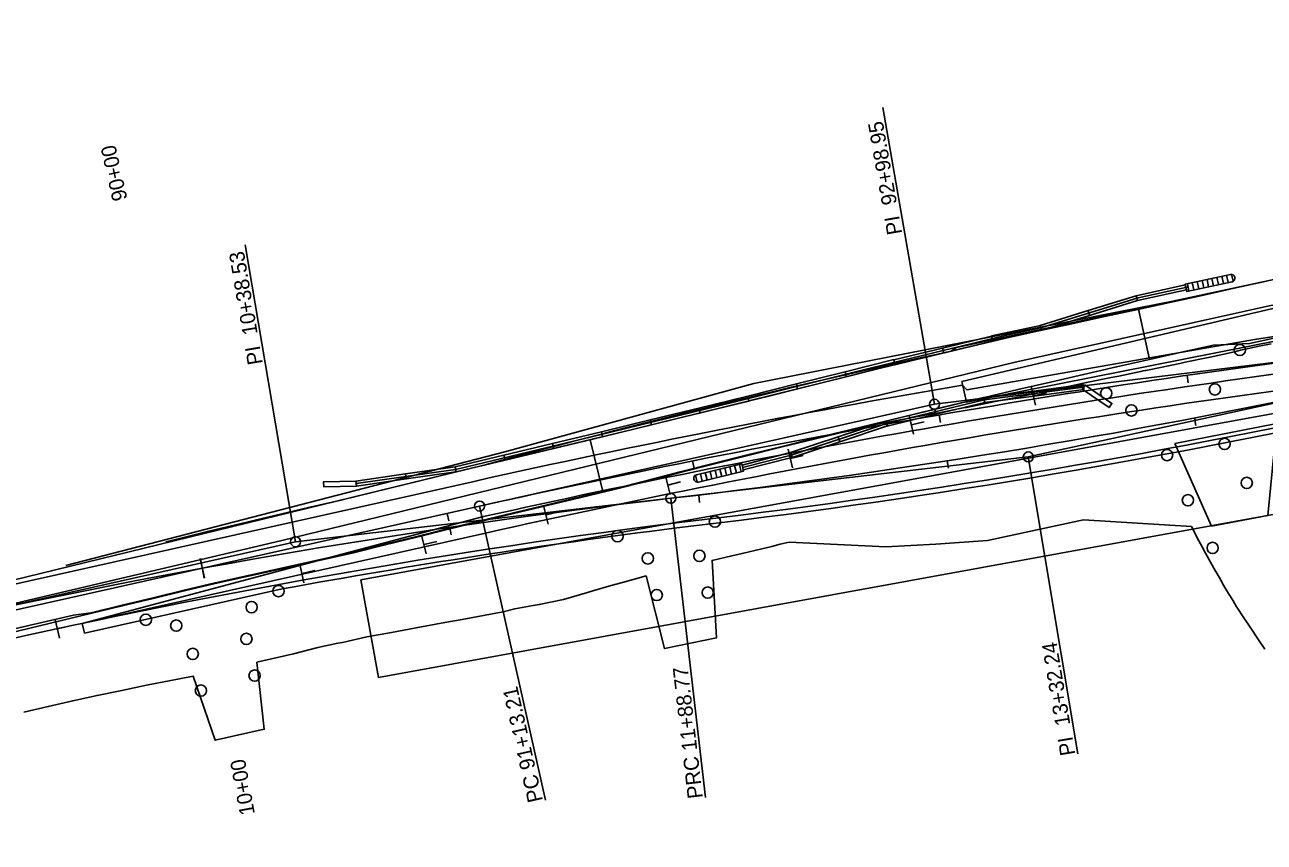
# Model space of a CAD drawing. Extents: x 1568809 to 1572786, y 728326 to 734907.
# Drawn here: x 1569227.8 to 1569721.8, y 731921.7 to 732247.4 of the extents above; entities that cross this region are included whole.
import ezdxf

# ---------------------------------------------------------------- set-up
doc = ezdxf.new("R2010")
doc.units = 0
for name, color, linetype in [('R_Horz Alg', 7, 'Continuous'), ('R_Horz Alg Annot', 7, 'Continuous'), ('R_MOT', 7, 'Continuous'), ('R_No Plot', 7, 'Continuous'), ('R_Proposed Const Limits_Fill', 7, 'Continuous'), ('R_Proposed Const Limits_Hand', 7, 'Continuous'), ('R_Proposed Road_Shoulder', 7, 'Continuous'), ('R_Striping', 7, 'Continuous')]:
    doc.layers.add(name, color=color, linetype=linetype)

msp = doc.modelspace()

# ---------------------------------------------------------------- linework, layer by layer
at = {"layer": 'R_Horz Alg'}
for p, q in [((1569485.27, 732058.75), (1569485.27, 732058.75)), ((1568810.94, 731921.74), (1569409.1, 732055.64))]:
    msp.add_line(p, q, dxfattribs=at)
for centre, radius, start, end in [((1570243.51, 728328.17), 3819.72, 97.05, 102.61775), ((1569155.89, 734904.54), 2864.79, 276.60226, 282.33591), ((1569814.66, 729212.96), 2864.79, 96.60226, 102.61775)]:
    msp.add_arc(centre, radius, start, end, dxfattribs=at)
at = {"layer": 'R_Horz Alg Annot'}
for p, q in [((1569590.36, 732096.21), (1569774.69, 732119.01)), ((1569627.78, 732075.25), (1569767.93, 732105.9)), ((1569409.1, 732055.64), (1569590.36, 732096.21)), ((1569485.27, 732058.75), (1569627.78, 732075.25)), ((1569335.75, 732041.44), (1569485.27, 732058.75)), ((1569188.86, 732008.56), (1569335.75, 732041.44))]:
    msp.add_line(p, q, dxfattribs=at)
for points in [[(1569590.36, 732096.21), (1569569.86, 732214.45)], [(1569335.75, 732041.44), (1569315.71, 732159.76)], [(1569691.49, 732104.76), (1569691.05, 732107.72)], [(1569592.82, 732089.01), (1569592.31, 732091.97)], [(1569694.58, 732087.8), (1569694.01, 732090.75)], [(1569494.59, 732070.69), (1569494.01, 732073.63)], [(1569595.95, 732070.72), (1569595.49, 732073.68)], [(1569627.78, 732075.25), (1569647.53, 731956.88)], [(1569485.27, 732058.75), (1569499.07, 731939.55)], [(1569496.78, 732057.09), (1569496.42, 732060.06)], [(1569409.1, 732055.64), (1569435.32, 731938.54)], [(1569396.87, 732049.82), (1569396.21, 732052.75)], [(1569397.7, 732044.21), (1569397.26, 732047.18)], [(1569297.75, 732034.81), (1569299.5, 732027)], [(1569297.88, 732034.82), (1569299.32, 732026.95)]]:
    msp.add_lwpolyline(points, dxfattribs=at)
for centre in [(1569590.36, 732096.21), (1569627.78, 732075.25), (1569485.27, 732058.75), (1569485.27, 732058.75), (1569409.1, 732055.64), (1569335.75, 732041.44)]:
    msp.add_circle(centre, 2, dxfattribs=at)
at = {"layer": 'R_MOT'}
for p, q in [((1569706.82, 732147.65), (1569707.46, 732144.71)), ((1569708.79, 732148), (1569709.4, 732145.2)), ((1569691.05, 732142.89), (1569671.51, 732138.61)), ((1569691.19, 732144.26), (1569691.82, 732141.32)), ((1569693.14, 732144.68), (1569693.78, 732141.75)), ((1569695.1, 732145.1), (1569695.73, 732142.17)), ((1569697.05, 732145.53), (1569697.69, 732142.59)), ((1569699.01, 732145.95), (1569699.64, 732143.02)), ((1569700.96, 732146.37), (1569701.6, 732143.44)), ((1569702.92, 732146.8), (1569703.55, 732143.87)), ((1569704.87, 732147.22), (1569705.51, 732144.29)), ((1569671.51, 732138.61), (1569632.82, 732126.67)), ((1569671.76, 732134.06), (1569676.06, 732114.11)), ((1569676.06, 732114.11), (1569671.76, 732134.06)), ((1569610.17, 732097.93), (1569649.84, 732103.07)), ((1569630.64, 732095.82), (1569628.94, 732103.28)), ((1569629.9, 732099.55), (1569634.99, 732100.71)), ((1569533.31, 732075.99), (1569571.3, 732088.52)), ((1569582.02, 732084.27), (1569580.26, 732091.71)), ((1569581.26, 732087.99), (1569586.34, 732089.2)), ((1569458.16, 732061.44), (1569453.21, 732082.11)), ((1569453.21, 732082.11), (1569458.16, 732061.44)), ((1569533.8, 732070.87), (1569532.01, 732078.3)), ((1569513.93, 732071.04), (1569533.31, 732075.99)), ((1569533.02, 732074.59), (1569538.09, 732075.82)), ((1569399.55, 732070.26), (1569359.95, 732064.64)), ((1569497.82, 732065.6), (1569497.11, 732068.51)), ((1569499.76, 732066.07), (1569499.06, 732068.98)), ((1569501.71, 732066.54), (1569501, 732069.45)), ((1569503.65, 732067.01), (1569502.94, 732069.92)), ((1569505.59, 732067.48), (1569504.89, 732070.39)), ((1569507.54, 732067.95), (1569506.83, 732070.86)), ((1569509.48, 732068.42), (1569508.78, 732071.34)), ((1569511.43, 732068.89), (1569510.72, 732071.81)), ((1569513.37, 732069.36), (1569512.66, 732072.28)), ((1569485, 732060.31), (1569483.12, 732067.73)), ((1569484.17, 732064.03), (1569489.23, 732065.31)), ((1569495.86, 732065.19), (1569495.18, 732067.97)), ((1569436.38, 732048.39), (1569434.62, 732055.84)), ((1569435.61, 732052.12), (1569440.69, 732053.32)), ((1569387.83, 732036.61), (1569386, 732044.03)), ((1569387.02, 732040.33), (1569392.09, 732041.58)), ((1569339.08, 732025.08), (1569337.44, 732032.55)), ((1569338.37, 732028.82), (1569343.47, 732029.94)), ((1569241.62, 732003.04), (1569239.89, 732010.49)), ((1569240.87, 732006.77), (1569245.96, 732007.95))]:
    msp.add_line(p, q, dxfattribs=at)
for points in [[(1569708.34, 732147.97), (1569690.26, 732144.06), (1569690.9, 732141.12), (1569708.98, 732145.04)], [(1569671.76, 732134.06), (1569658.27, 732131.14), (1569645.1, 732128.3), (1569631.94, 732125.46), (1569618.77, 732122.62), (1569605.47, 732119.41), (1569592.17, 732116.2), (1569578.87, 732112.99), (1569565.57, 732109.79), (1569551.83, 732106.36), (1569538.09, 732102.93), (1569524.35, 732099.51), (1569510.61, 732096.08), (1569497.27, 732092.83), (1569483.93, 732089.58), (1569470.58, 732086.32), (1569457.24, 732083.07), (1569453.21, 732082.11)], [(1569632.82, 732126.67), (1569618.55, 732123.6), (1569565.33, 732110.76), (1569510.38, 732097.05), (1569457, 732084.04), (1569403.99, 732071.35), (1569399.55, 732070.26)], [(1569458.16, 732061.44), (1569462.7, 732062.51), (1569475.87, 732065.88), (1569489.04, 732069.24), (1569502.21, 732072.61), (1569515.38, 732075.97), (1569529.13, 732079.31), (1569542.88, 732082.66), (1569556.63, 732086.01), (1569570.38, 732089.35), (1569583.67, 732092.52), (1569596.96, 732095.69), (1569610.25, 732098.87), (1569623.54, 732102.04), (1569636.67, 732105.06), (1569649.8, 732108.07), (1569662.93, 732111.09), (1569676.06, 732114.11)], [(1569571.3, 732088.52), (1569610.17, 732097.93)], [(1569571.3, 732088.52), (1569571.3, 732088.52)], [(1569496.31, 732065.23), (1569514.29, 732069.58), (1569513.58, 732072.5), (1569495.6, 732068.14)]]:
    msp.add_lwpolyline(points, dxfattribs=at)
for points in [[(1569670.82, 732139.48), (1569690.36, 732143.76), (1569690.78, 732141.81), (1569671.25, 732137.53)], [(1569651.64, 732133.53), (1569670.75, 732139.42), (1569671.34, 732137.51), (1569652.23, 732131.62)], [(1569632.53, 732127.63), (1569651.64, 732133.53), (1569652.23, 732131.62), (1569633.12, 732125.72)], [(1569613.06, 732123.43), (1569632.61, 732127.65), (1569633.03, 732125.7), (1569613.48, 732121.48)], [(1569593.62, 732118.61), (1569613.07, 732123.3), (1569613.53, 732121.36), (1569594.09, 732116.67)], [(1569574.18, 732113.92), (1569593.62, 732118.61), (1569594.09, 732116.67), (1569574.65, 732111.98)], [(1569554.75, 732109.15), (1569574.16, 732113.99), (1569574.64, 732112.05), (1569555.23, 732107.21)], [(1569535.35, 732104.31), (1569554.75, 732109.15), (1569555.23, 732107.21), (1569535.83, 732102.37)], [(1569515.94, 732099.47), (1569535.35, 732104.31), (1569535.83, 732102.37), (1569516.42, 732097.53)], [(1569629.88, 732101.49), (1569649.72, 732104.06), (1569649.97, 732102.08), (1569630.14, 732099.51)], [(1569649.28, 732102.25), (1569659.99, 732094.89), (1569661.13, 732096.54), (1569650.41, 732103.89)], [(1569496.52, 732094.7), (1569515.95, 732099.44), (1569516.43, 732097.5), (1569496.99, 732092.76)], [(1569590.5, 732094.2), (1569609.94, 732098.9), (1569610.41, 732096.96), (1569590.97, 732092.25)], [(1569610.05, 732098.92), (1569629.88, 732101.49), (1569630.14, 732099.51), (1569610.3, 732096.94)], [(1569477.09, 732089.97), (1569496.52, 732094.7), (1569496.99, 732092.76), (1569477.56, 732088.02)], [(1569571.06, 732089.49), (1569590.5, 732094.2), (1569590.97, 732092.25), (1569571.53, 732087.55)], [(1569457.66, 732085.23), (1569477.09, 732089.97), (1569477.56, 732088.02), (1569458.13, 732083.29)], [(1569551.99, 732083.21), (1569570.99, 732089.47), (1569571.61, 732087.57), (1569552.62, 732081.31)], [(1569438.21, 732080.57), (1569457.66, 732085.23), (1569458.13, 732083.28), (1569438.68, 732078.63)], [(1569533, 732076.94), (1569551.99, 732083.21), (1569552.62, 732081.31), (1569533.63, 732075.04)], [(1569418.76, 732075.92), (1569438.21, 732080.57), (1569438.68, 732078.63), (1569419.23, 732073.97)], [(1569399.31, 732071.26), (1569418.76, 732075.92), (1569419.23, 732073.97), (1569399.78, 732069.31)], [(1569513.69, 732072.01), (1569533.06, 732076.96), (1569533.56, 732075.02), (1569514.18, 732070.07)], [(1569359.81, 732065.63), (1569379.61, 732068.44), (1569379.89, 732066.46), (1569360.09, 732063.65)], [(1569379.61, 732068.44), (1569399.41, 732071.25), (1569399.69, 732069.27), (1569379.89, 732066.46)], [(1569359.97, 732063.64), (1569346.97, 732063.37), (1569346.93, 732065.37), (1569359.93, 732065.64)]]:
    msp.add_lwpolyline(points, close=True, dxfattribs=at)
for centre in [(1569712.09, 732117.84), (1569702.15, 732102.13), (1569658.83, 732100.58), (1569668.85, 732093.77), (1569683.08, 732075.97), (1569706, 732080.43), (1569714.82, 732064.86), (1569691.41, 732057.99), (1569502.9, 732049.47), (1569464.05, 732043.67), (1569701.25, 732038.99), (1569476.15, 732034.8), (1569496.68, 732035.82), (1569328.94, 732021.77), (1569479.68, 732020.22), (1569500.01, 732021.2), (1569318.25, 732015.39), (1569276.08, 732010.35), (1569288.2, 732008.03), (1569316.14, 732002.74), (1569294.76, 731996.77), (1569319.41, 731988.1), (1569298.03, 731982.14)]:
    msp.add_circle(centre, 2.25, dxfattribs=at)
for centre, start, end in [((1569708.66, 732146.51), 282.2318, 102.2318), ((1569495.95, 732066.69), 103.6134, 283.6134)]:
    msp.add_arc(centre, 1.5, start, end, dxfattribs=at)
at = {"layer": 'R_No Plot'}
for p, q in [((1569599.2, 732118.84), (1569772.9, 732155.99)), ((1569691.05, 732142.89), (1569671.51, 732138.61)), ((1569671.51, 732138.61), (1569632.82, 732126.67)), ((1569596.97, 732117.38), (1569599.2, 732118.84)), ((1569603.22, 732101.96), (1569601.54, 732103.8)), ((1569610.17, 732097.93), (1569649.84, 732103.07)), ((1569533.31, 732075.99), (1569571.3, 732088.52)), ((1569513.93, 732071.04), (1569533.31, 732075.99)), ((1569177.82, 732015.14), (1569410.85, 732071.97)), ((1569399.55, 732070.26), (1569359.95, 732064.64)), ((1569406.9, 732065.5), (1569178.01, 732014.27)), ((1569410.6, 732051.44), (1569250.71, 732008.91)), ((1569411.51, 732044.9), (1569250.71, 732008.91)), ((1569486.67, 732046.83), (1569486.65, 732046.83)), ((1569486.67, 732046.83), (1569486.65, 732046.83)), ((1569251.58, 732005), (1569330.38, 732022.64)), ((1569251.58, 732005), (1569330.38, 732022.64)), ((1569254.28, 732013.13), (1569247.28, 732012.21)), ((1569250.71, 732008.91), (1569251.58, 732005)), ((1569250.71, 732008.91), (1569251.58, 732005))]:
    msp.add_line(p, q, dxfattribs=at)
for points in [[(1570014.9, 732172.44), (1570001.94, 732170.63), (1569988.99, 732168.82), (1569975.8, 732167.05), (1569962.62, 732165.29), (1569949.43, 732163.52), (1569936.25, 732161.75), (1569923.33, 732159.85), (1569910.41, 732157.95), (1569897.49, 732156.06), (1569884.56, 732154.16), (1569871.51, 732151.99), (1569858.45, 732149.82), (1569845.39, 732147.64), (1569832.33, 732145.47), (1569819.33, 732143.14), (1569806.33, 732140.81), (1569793.33, 732138.48), (1569781.46, 732134.16), (1569768.14, 732131.46), (1569753.99, 732127.44), (1569718.69, 732122.21), (1569603.22, 732101.96)], [(1569728.75, 732123.25), (1569716, 732120.44), (1569701.56, 732119.73), (1569688.81, 732116.92), (1569676.06, 732114.11), (1569662.93, 732111.09), (1569636.67, 732105.06), (1569623.54, 732102.04), (1569610.25, 732098.87), (1569596.96, 732095.69), (1569583.67, 732092.52), (1569570.38, 732089.35), (1569556.63, 732086.01), (1569542.88, 732082.66), (1569529.13, 732079.31), (1569515.38, 732075.97), (1569502.21, 732072.61), (1569489.04, 732069.24), (1569475.87, 732065.88), (1569462.7, 732062.51), (1569449.34, 732059.34), (1569435.99, 732056.16), (1569422.64, 732052.99), (1569409.29, 732049.82), (1569396.68, 732046.69), (1569384.08, 732043.56), (1569371.47, 732040.43), (1569358.87, 732037.3), (1569345.08, 732034.24), (1569331.29, 732031.19), (1569317.51, 732028.13), (1569303.72, 732025.08), (1569291.36, 732022.09), (1569279, 732019.1), (1569266.64, 732016.12), (1569254.28, 732013.13)], [(1569632.82, 732126.67), (1569618.55, 732123.6), (1569565.33, 732110.76), (1569510.38, 732097.05), (1569457, 732084.04), (1569403.99, 732071.35), (1569399.55, 732070.26)], [(1569724.56, 732120.33), (1569719.73, 732119.38), (1569712.39, 732117.8), (1569709.93, 732117.1), (1569700.27, 732115), (1569700.12, 732114.97), (1569699.52, 732114.84), (1569690.29, 732112.95), (1569688.12, 732112.45), (1569680.48, 732110.87), (1569675.96, 732109.99), (1569674.56, 732109.72), (1569673.6, 732109.51), (1569673.59, 732109.51), (1569672.61, 732109.29), (1569670.65, 732108.86), (1569663.83, 732107.39), (1569660.84, 732106.84), (1569651.67, 732104.97), (1569651.02, 732104.83), (1569641.22, 732102.73), (1569639.55, 732102.39), (1569631.42, 732100.64), (1569627.43, 732099.79), (1569621.6, 732098.68), (1569615.28, 732097.4), (1569603.13, 732094.98), (1569601.98, 732094.76), (1569592.15, 732092.87), (1569590.97, 732092.64), (1569582.32, 732091.02), (1569578.81, 732090.37), (1569566.17, 732088.07)], [(1569571.3, 732088.52), (1569610.17, 732097.93)], [(1569566.17, 732088.07), (1569556.66, 732085.76), (1569542.91, 732082.41), (1569529.16, 732079.07), (1569515.41, 732075.72), (1569502.24, 732072.36), (1569489.07, 732068.99), (1569475.9, 732065.63), (1569462.73, 732062.27), (1569449.38, 732059.09), (1569436.03, 732055.92), (1569422.67, 732052.74), (1569409.32, 732049.57), (1569396.72, 732046.44), (1569384.11, 732043.31), (1569371.51, 732040.18), (1569358.9, 732037.05), (1569345.12, 732034), (1569331.33, 732030.94), (1569317.54, 732027.89), (1569303.75, 732024.83), (1569291.39, 732021.84), (1569279.03, 732018.86), (1569266.67, 732015.87), (1569094.11, 731974.15)], [(1569571.3, 732088.52), (1569571.3, 732088.52)], [(1569692.82, 732047.58), (1569649.72, 732050.12), (1569611.57, 732041.99), (1569590.97, 732040.46), (1569570.96, 732039.46), (1569532.47, 732041.3)], [(1569532.47, 732041.3), (1569570.96, 732039.46), (1569590.97, 732040.46), (1569611.57, 732041.99), (1569649.72, 732050.12), (1569692.82, 732047.58)], [(1569722.06, 731998.68), (1569719.24, 732002.82), (1569716.41, 732006.97), (1569713.63, 732011.14), (1569710.93, 732015.35), (1569710.8, 732015.56), (1569709.37, 732017.87), (1569708.06, 732020.03), (1569707.95, 732020.21), (1569706.55, 732022.55), (1569705.24, 732024.79), (1569705.17, 732024.92), (1569703.8, 732027.29), (1569702.47, 732029.61), (1569702.43, 732029.68), (1569701.07, 732032.07), (1569699.72, 732034.47), (1569699.72, 732034.49), (1569698.38, 732036.92), (1569697.06, 732039.36), (1569697.03, 732039.41), (1569695.75, 732041.83), (1569694.47, 732044.32), (1569694.42, 732044.42), (1569692.82, 732047.58)], [(1569692.82, 732047.58), (1569694.42, 732044.42), (1569694.47, 732044.32), (1569695.75, 732041.83), (1569697.03, 732039.41), (1569697.06, 732039.36), (1569698.38, 732036.92), (1569699.72, 732034.49), (1569699.72, 732034.47), (1569701.07, 732032.07), (1569702.43, 732029.68), (1569702.47, 732029.61), (1569703.8, 732027.29), (1569705.17, 732024.92), (1569705.24, 732024.79), (1569706.55, 732022.55), (1569707.95, 732020.21), (1569708.06, 732020.03), (1569709.37, 732017.87), (1569710.8, 732015.56), (1569710.93, 732015.35), (1569713.63, 732011.14), (1569716.41, 732006.97), (1569719.24, 732002.82), (1569722.06, 731998.68)], [(1569532.47, 732041.3), (1569528.91, 732040.43), (1569525.62, 732039.54), (1569525, 732039.4), (1569519.28, 732038.12), (1569513.68, 732036.78), (1569509.65, 732035.8), (1569501.75, 732034.01), (1569503.47, 732003.12), (1569482.75, 731998.91), (1569475.46, 732027.86), (1569466.08, 732025.16), (1569461.56, 732024.07), (1569454.27, 732021.91), (1569452.06, 732021.2), (1569442.54, 732018.45), (1569442.5, 732018.44), (1569432.87, 732016.41), (1569430.51, 732016.02), (1569423.12, 732014.72), (1569418.52, 732013.56), (1569413.41, 732012.54), (1569403.56, 732010.76), (1569393.72, 732008.94), (1569383.88, 732007.15), (1569374.03, 732005.34), (1569364.19, 732003.53), (1569354.43, 732001.36), (1569352.56, 732001.02), (1569344.64, 731999.32), (1569334.95, 731996.81), (1569320.33, 731993.46), (1569323.24, 731966.73), (1569303.72, 731962.36), (1569294.93, 731987.9), (1569286.1, 731986.17), (1569276.28, 731984.24), (1569266.48, 731982.24), (1569256.68, 731980.24), (1569246.92, 731978.07), (1569237.18, 731975.79), (1569227.44, 731973.53)], [(1569227.44, 731973.53), (1569237.18, 731975.79), (1569246.92, 731978.07), (1569256.68, 731980.24), (1569266.48, 731982.24), (1569276.28, 731984.24), (1569286.1, 731986.17), (1569294.93, 731987.9), (1569303.72, 731962.36), (1569323.24, 731966.73), (1569320.33, 731993.46), (1569334.95, 731996.81), (1569344.64, 731999.32), (1569352.56, 732001.02), (1569354.43, 732001.36), (1569364.19, 732003.53), (1569374.03, 732005.34), (1569383.88, 732007.15), (1569393.72, 732008.94), (1569403.56, 732010.76), (1569413.41, 732012.54), (1569418.52, 732013.56), (1569423.12, 732014.72), (1569430.51, 732016.02), (1569432.87, 732016.41), (1569442.5, 732018.44), (1569442.54, 732018.45), (1569452.06, 732021.2), (1569454.27, 732021.91), (1569461.56, 732024.07), (1569466.08, 732025.16), (1569475.46, 732027.86), (1569482.75, 731998.91), (1569503.47, 732003.12), (1569501.75, 732034.01), (1569509.65, 732035.8), (1569513.68, 732036.78), (1569519.28, 732038.12), (1569525, 732039.4), (1569525.62, 732039.54), (1569528.91, 732040.43), (1569532.47, 732041.3)], [(1569247.28, 732012.21), (1569223.69, 732006.71), (1569200.1, 732001.2), (1569176.81, 731995.63), (1569153.51, 731990.05), (1569139.68, 731986.8), (1569125.85, 731983.54), (1569112.02, 731980.28), (1569093.68, 731975.96)]]:
    msp.add_lwpolyline(points, dxfattribs=at)
for points in [[(1569601.29, 732105.28), (1569603.2, 732097.08), (1569764.97, 732129.06), (1569757.55, 732142)], [(1569361.7, 732026.33), (1569753.23, 732097.58), (1569760.32, 732058.65), (1569368.79, 731987.39)], [(1569686.14, 732080.55), (1569700.8, 732047.66), (1569723.22, 732051.87), (1569726.84, 732088.5)]]:
    msp.add_lwpolyline(points, close=True, dxfattribs=at)
for centre, radius, start, end in [((1570242.6, 728334.71), 3808.72, 97.05, 102.61775), ((1570380.82, 728500.81), 3700.54, 102.22905, 105.19563), ((1570243.51, 728328.17), 3808.72, 97.05, 102.61775), ((1570243.76, 728326.23), 3831.78, 99.6486, 102.61518), ((1569155.89, 734904.54), 2876.79, 276.60226, 282.33591), ((1569155.89, 734904.54), 2876.79, 276.60226, 282.33592), ((1569844.49, 729218.01), 2851.36, 97.20901, 100.38744), ((1569844.49, 729218.01), 2851.36, 97.20901, 100.38744)]:
    msp.add_arc(centre, radius, start, end, dxfattribs=at)
at = {"layer": 'R_Proposed Const Limits_Fill'}
msp.add_lwpolyline([(1569563.14, 732087.59), (1569566.63, 732088.19), (1569572.48, 732089.22), (1569578.81, 732090.37), (1569582.32, 732091.02), (1569590.97, 732092.64), (1569592.15, 732092.87), (1569601.98, 732094.76), (1569603.13, 732094.98), (1569615.28, 732097.4), (1569621.6, 732098.68), (1569627.43, 732099.79), (1569631.42, 732100.64), (1569639.55, 732102.39), (1569641.22, 732102.73), (1569651.02, 732104.83), (1569651.67, 732104.97), (1569660.84, 732106.84), (1569663.83, 732107.39), (1569670.65, 732108.86), (1569672.61, 732109.29), (1569673.59, 732109.51), (1569673.6, 732109.51), (1569674.56, 732109.72), (1569675.96, 732109.99), (1569680.48, 732110.87), (1569688.12, 732112.45), (1569690.29, 732112.95), (1569699.52, 732114.84), (1569700.12, 732114.97), (1569700.27, 732115), (1569709.93, 732117.1), (1569712.39, 732117.8), (1569719.73, 732119.38), (1569724.56, 732120.33)], dxfattribs=at)
at = {"layer": 'R_Proposed Const Limits_Hand'}
msp.add_lwpolyline([(1569244.23, 732032.04), (1569419.19, 732077.21), (1569518.33, 732104.48), (1569686.05, 732137.42)], dxfattribs=at)
at = {"layer": 'R_Proposed Road_Shoulder'}
msp.add_line((1569483.66, 732072.66), (1569483.66, 732072.66), dxfattribs=at)
msp.add_line((1569483.66, 732072.66), (1569483.66, 732072.66), dxfattribs=at)
at = {"layer": 'R_Striping'}
for points in [[(1569091.81, 731985.64), (1569147.99, 731999.1), (1569330.25, 732041.98), (1569622.48, 732112.98), (1569698.68, 732129.84), (1569723.78, 732135.38), (1569804.21, 732150.59), (1569837.55, 732156.52), (1569935.04, 732171.96), (1570097.77, 732194.1), (1570522.6, 732247.41)], [(1569284.5, 732041.74), (1569284.16, 732041.41), (1569300.65, 732045.51), (1569314.09, 732048.68), (1569327.53, 732051.86), (1569340.97, 732055.03), (1569354.41, 732058.2), (1569354.36, 732058.19), (1569366.83, 732061.23), (1569379.29, 732064.28), (1569391.76, 732067.33), (1569404.23, 732070.38), (1569417.48, 732073.55), (1569430.73, 732076.72), (1569443.98, 732079.9), (1569457.24, 732083.07), (1569470.58, 732086.32), (1569483.93, 732089.58), (1569497.27, 732092.83), (1569510.61, 732096.08), (1569524.35, 732099.51), (1569538.09, 732102.93), (1569551.83, 732106.36), (1569565.57, 732109.79), (1569578.87, 732112.99), (1569592.17, 732116.2), (1569605.47, 732119.41), (1569618.77, 732122.62), (1569631.94, 732125.46), (1569645.1, 732128.3), (1569658.27, 732131.14), (1569671.43, 732133.99), (1569684.24, 732136.79), (1569697.05, 732139.6), (1569709.87, 732142.41), (1569722.68, 732145.21)]]:
    msp.add_lwpolyline(points, dxfattribs=at)
for centre, radius, start, end in [((1569155.89, 734904.54), 2874.79, 276.60226, 282.33591), ((1569155.89, 734904.54), 2876.79, 276.60226, 282.33591), ((1569844.49, 729218.01), 2853.36, 97.20901, 103.22449), ((1569844.49, 729218.01), 2851.36, 97.20901, 100.38744)]:
    msp.add_arc(centre, radius, start, end, dxfattribs=at)

# ---------------------------------------------------------------- texts
at = {"layer": 'R_Horz Alg Annot'}
for s, rotation, p in [('PI  92+98.95', 99.8339, (1569577.54, 732164.28)), ('90+00', 102.6177, (1569268.79, 732177.94)), ('PI  10+38.53', 99.61, (1569322.71, 732112.45)), ('PI  13+32.24', 99.4691, (1569646.54, 731956.72)), ('PRC 11+88.77', 96.6023, (1569498.08, 731939.43)), ('PC 91+13.21', 102.6177, (1569434.34, 731938.32)), ('10+00', 100.3777, (1569319.57, 731933.06))]:
    msp.add_text(s, height=6, rotation=rotation, dxfattribs=at).set_placement(p)

doc.saveas('drawing.dxf')
